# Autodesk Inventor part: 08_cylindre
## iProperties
Created: 2002-11
Part Number: 08_cylindre
Material: Acier inoxydable - 440C
Document SubType Name: Modélisation
Designer: FIEVET
Control State: 0
Master: False
Checked Out: False
Shininess: 70.0
Length Units: 11269
Angle Units: 11279
Time Units: 11290
Mass Units: 11283
Length Display Precision: 3
Angle Display Precision: 2
Compacted: True
Density: 7.75
Volumn: 3.0381818954091346
Area: 32.423660378250354
PropertySet Name: Model Information
Author: FIEVET
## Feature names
1. Révolution1 [Revolution]
